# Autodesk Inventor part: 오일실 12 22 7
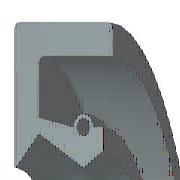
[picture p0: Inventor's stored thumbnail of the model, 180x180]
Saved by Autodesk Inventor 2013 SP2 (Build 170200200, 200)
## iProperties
Created: 2012-02
Part Number: 오일실 12 22 7
Material: 고무
Description: 오일-실
Document SubType Name: Modeling
Standard: KS B 2804
Designer: mduedu
Standards Organization: KS
Language: ko-KR
Size Designation: D - 12 22 7
Categories: <MemberInstance><Categories><Category DisplayName="샤프트 부품" InternalName="7f7aeb1f-a693-4053-b835-cee3144e0d98" Mnemonic="SHFT"><Category DisplayName="실링" Intern
Density: 0.93 g/cm^3
Mass: 1.25383 g
Surface Area: 18.4996 cm^2
Volume: 1.3482 cm^3
IsCustomPart: 1
Author: mduedu
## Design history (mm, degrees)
revolve "본체" stored, may be unused: angle "d17" = 90 deg
revolve "스프링1" stored, may be unused: angle "d18" = 90 deg
body "Solid1"
sketch "스케치1"
  geometry: L1 (0, 11)-(7, 11); L2 (7, 9.25)-(1.75, 9.25); L3 (1.75, 7.75)-(4.9, 6); L4 (4.9, 6)-(0, 6); L5 (0, 0)-(9.586, 0) reference; L6 (4.9, 6)-(6.3, 6.875); L7 (0, 18)-(0, -3) reference; L8 (-1.941, 0)-(11.507, 0) reference; L9 (4.2, 8.1)-(1.75, 8.59); L10 (1.75, 8.59)-(1.75, 9.25); L11 (0, 11)-(0, 6.088); L12 (4.9, 6)-(0, 6); L13 (1.75, 7.75)-(0.152, 6.028); L14 (7, 11)-(7, 9.25); L15 (5.6, 8.1)-(6.3, 8.1); L16 (6.3, 8.1)-(6.3, 6.875); C1 r 0.455 at (4.9, 8.1); A1 r 0.7 centre (4.9, 8.1) between (5.6, 8.1) and (4.2, 8.1); A2 r 0.088 centre (0.088, 6.088) between (0, 6.088) and (0.152, 6.028); 1 further point
  constraints: 28 end point, 5 horizontal alignment, 5 point on line, 4 point on circle, 4 vertical alignment, 3 centre point, 3 tangent, 2 collinear, 2 horizontal, 2 perpendicular, 1 coincident, 1 parallel
  dimensions: "d0" = 22 diameter of L1 L5 (= SD2); "d1" = 1.75 distance of L1.end L2.start (= SD); "d2" = 0.91 diameter of C1 (= SPDI); "d3" = 1.4 diameter of A1 (= SPDA); "d4" = 12 diameter of L3.end L5 (= NND); "d5" = 15.5 diameter of L3.start L5 (= TKDM); "d7" = 17.18 diameter of L9.end L5 (= TKDM + 0.24 x SWDT); "d8" = 1.75 distance between parallel lines of L11 L10 (= SD); "d9" = 4.9 distance from line of L11 C1.centre (= SPDST); "d10" = 16.2 diameter of C1.centre L5 (= HLDM); "d11" = 0.0875 radius of A2 (= 0.25 x LAB); "d12" = 6.3 distance between parallel lines of L11 L16 (= SDI); "d13" = 13.75 diameter of L6.end L5 (= ABDM); "d14" = 7 distance from line of L11 L1.end (= SWDT)
fillet "모깎기1" dims "d6" = 0.3 (= RR)
other parameters: "SD2" = 22 [user parameter; used in 1 equation term], "SWDT" = 7 [user parameter; used in 2 equation terms], "RR" = 0.3 [user parameter; used in 1 equation term], "SD" = 1.75 [user parameter; used in 2 equation terms], "NND" = 12 [user parameter; used in 1 equation term], "SPDA" = 1.4 [user parameter; used in 1 equation term], "SPDI" = 0.91 [user parameter; used in 1 equation term], "TKDM" = 15.5 [user parameter; used in 2 equation terms], "HLDM" = 16.2 [user parameter; used in 1 equation term], "ABDM" = 13.75 [user parameter; used in 1 equation term], "SDI" = 6.3 [user parameter; used in 1 equation term], "SPDST" = 4.9 [user parameter; used in 1 equation term], "LAB" = 0.35 [user parameter; used in 1 equation term], "d15" = 0, "d16" = 0, "d19" = 0
